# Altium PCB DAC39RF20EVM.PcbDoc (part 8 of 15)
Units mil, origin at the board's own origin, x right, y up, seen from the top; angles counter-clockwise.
Board outline 6200 x 2716.54 mil, 16 copper layers (Top Layer, L2 GND, L3 PWR, L4 GND, L5 PWR, L6 GND, L7 SIG, L8 GND, L9 GND, L10 SIG, L11 GND, L12 PWR, L13 GND, L14 PWR, L15 GND, Bottom Layer), stack 76.97 mil thick; 766 components, 495 nets, 3414 pads, 2373 vias.
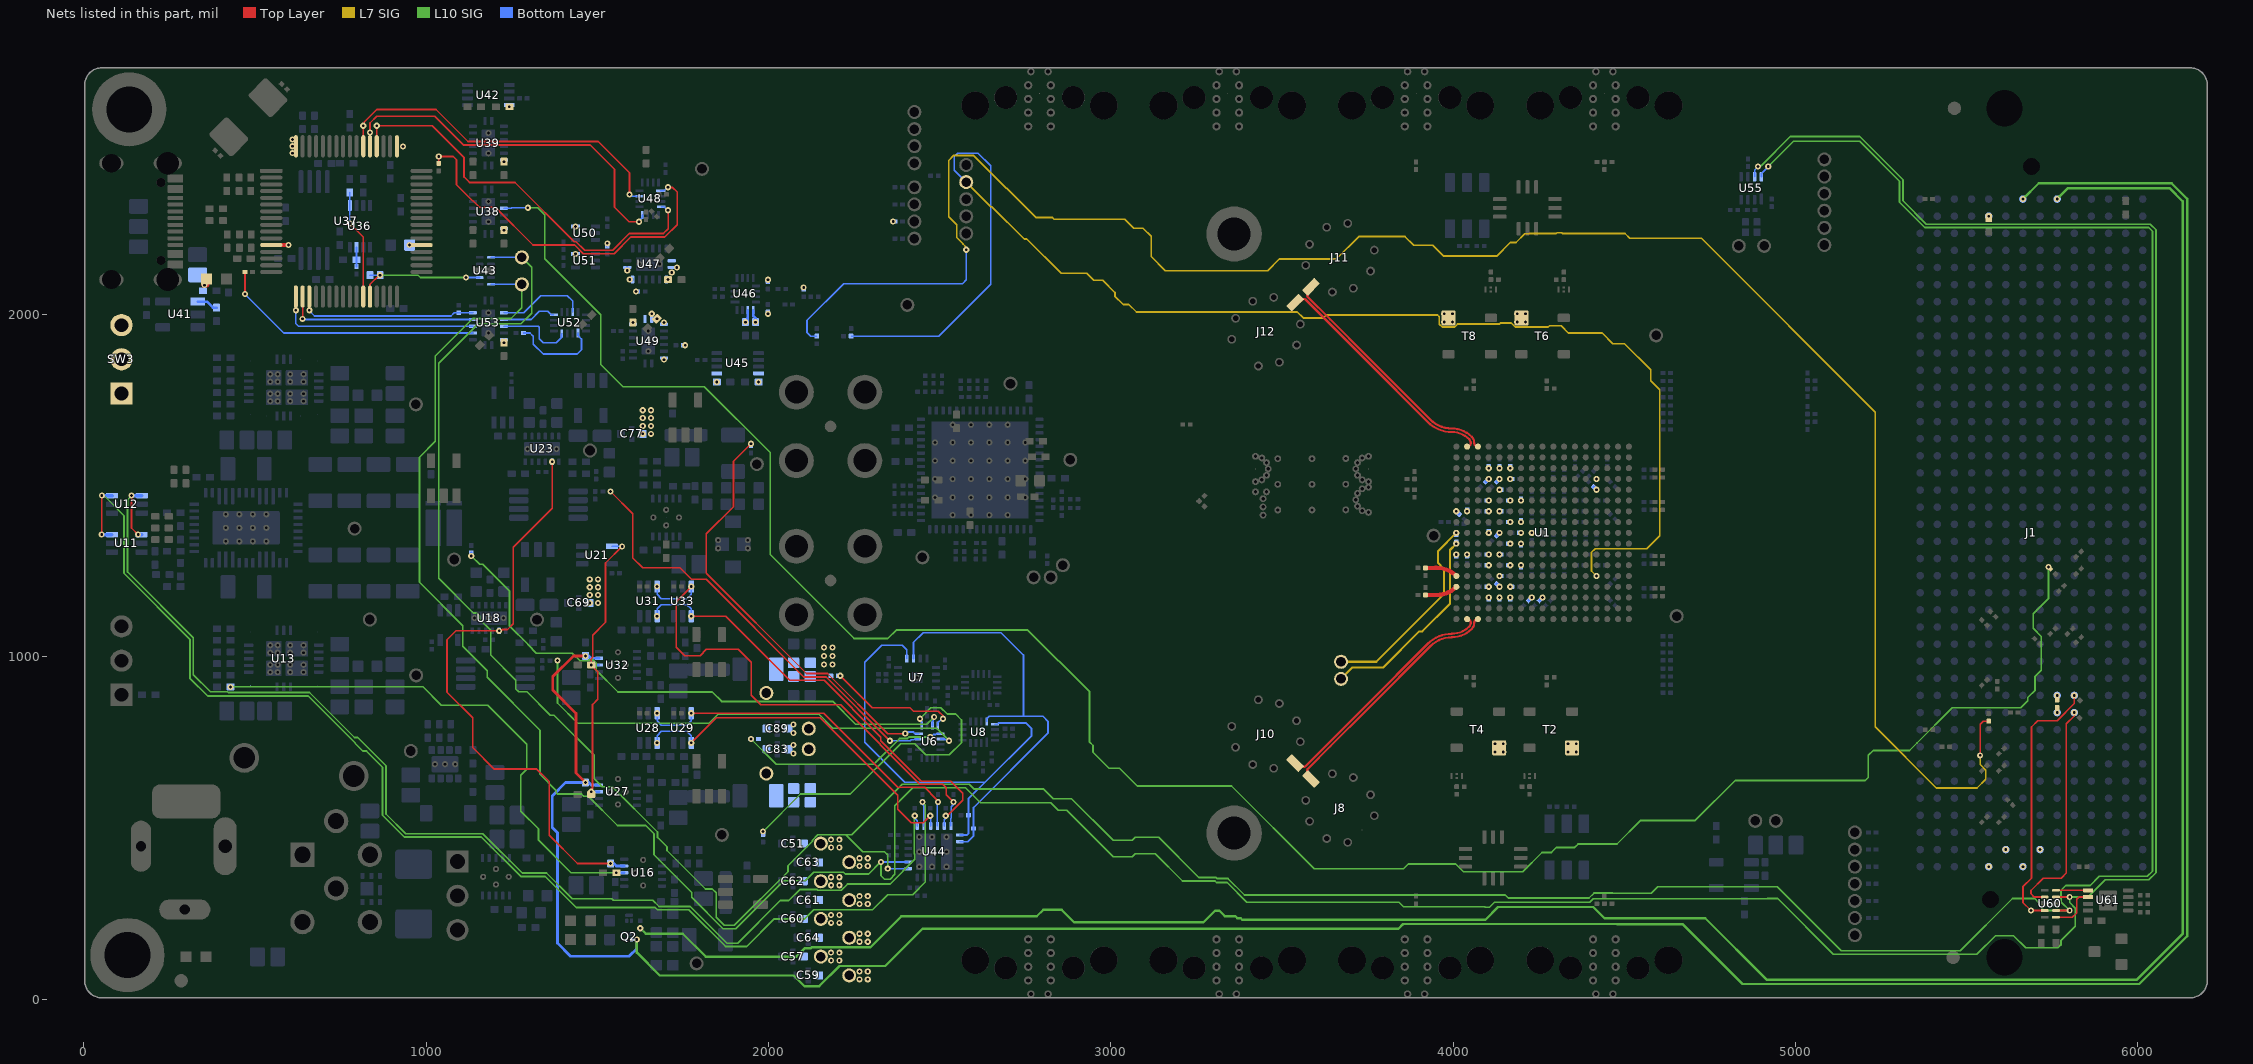
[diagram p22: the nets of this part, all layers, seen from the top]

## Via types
v1: diameter 18, hole 8, Top Layer to Bottom Layer, tented both sides, 2344 vias
v2: diameter 24, hole 12, Top Layer to Bottom Layer, tented both sides, 19 vias
v3: diameter 18, hole 8, Top Layer to Bottom Layer, tented bottom, 9 vias
v4: diameter 20, hole 10, Top Layer to Bottom Layer, tented both sides, 1 vias

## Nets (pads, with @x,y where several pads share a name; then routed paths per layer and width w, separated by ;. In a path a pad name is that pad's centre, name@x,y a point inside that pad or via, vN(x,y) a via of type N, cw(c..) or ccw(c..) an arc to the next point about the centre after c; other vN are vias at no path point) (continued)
PG-1p8V: R44.1 U16.4 U18.8 U23.8 | length 1756.8
  Top Layer w5: v1(1368.04,1569.83) 1368.04,1434.1 1253.99,1320.05 1253.99,1096.13 1237.52,1079.66 1222.91,1079.66 1220.98,1077.72 1215.14,1077.72 v1(1213.23,1075.81) 1087.27,1075.81 1060.61,1049.15 1060.61,897.35 1136.22,821.74 1136.22,734.92 1199.14,672 1322.98,672 1359.29,635.69 1359.29,478.91 1442.12,396.08 v1(1538.65,396.08)
  Bottom Layer w8: v1(1538.65,396.08) 1548.5,396.08 1555.58,388.99 U16.4@1578.58,388.99
PG-2p3V: R33.1 R45.1 U13.19 U16.3 | length 1533.3
  L10 SIG w5: v1(428.75,912.11) 990.96,912.11 1044.56,858.51 1180.09,858.51 1293.82,744.79 1293.82,671.96 1276.37,654.52 1276.37,549.02 1328.39,497 1328.39,464.12 1423.2,369.31 v1(1555.47,369.31)
  Bottom Layer w8: v1(1555.47,369.31) U16.3@1578.58,369.31
PG-C2M: J1.D1 R249.2 | length 7330.5
  L10 SIG w7: v1(1625.52,207.15) 1641.8,190.87 1749.69,190.87 1816.44,124.12 2081.09,124.12 2105.09,148.12 2122.78,148.12 2126.46,151.8 2297.87,151.8 2388.04,241.98 2783.51,241.98 2802.29,260.75 2856.47,260.75 2893.17,224.05 3270.01,224.05 3304.07,258.11 3316.91,258.11 3332.41,242.61 3363.13,242.61 3368.91,236.82 3378.95,236.82 3383.9,231.88 4094,231.88 4131.22,269.1 4409.18,269.1 4441.91,236.38 4736.03,236.38 4915.29,57.11 5996.92,57.11 6130.61,190.8 6130.61,2330.8 6092.38,2369.03 5795.97,2369.03 v1(5764.01,2337.07)
PG-M2C: J1.F1 Q2.1@1599.65,174.11 R68.1 R79.1 U27.4 U32.4 | length 8888.2
  Top Layer w8: v1(1465.29,632.63) 1437.66,660.25 1437.66,834.86 1369.67,902.85 1369.67,941.9 1430.39,1002.63 v1(1465.29,1002.63)
  L10 SIG w7: v1(1615.44,174.11) 1615.44,135.93 1682.25,69.12 2073.69,69.12 2105.02,37.8 2147.79,37.8 2206.86,96.87 2341.02,96.87 2449.88,205.73 3249.99,205.73 3250.4,205.32 3839.31,205.32 3853.18,219.19 3853.88,219.19 3854.07,219.38 4478.95,219.38 4479.13,219.19 4669.64,219.19 4844.71,44.11 6003.96,44.11 6143.61,183.76 6143.61,2337.84 6098.25,2383.2 5710.14,2383.2 v1(5664.01,2337.07)
  Bottom Layer w8: v1(1465.29,1002.63) 1475.13,1002.63 1482.21,995.54 U32.4@1505.21,995.54 ; U27.4@1505.21,625.54 1482.21,625.54 1475.13,632.63 v1(1465.29,632.63) 1407.43,632.63 1368.18,593.38 1368.18,501.72 1383.83,486.07 1383.83,163.62 1422.08,125.37 1592.76,125.37 1615.44,148.05 v1(1615.44,174.11) Q2.1@1599.65,174.11
PG-n1p8V: R69.1 R82.1 U21.4 U27.3 U32.3 | length 855.6
  Top Layer w5: v1(1482.1,605.86) 1484.59,608.34 1484.59,614.16 1485.71,615.28 1485.71,860.44 1501.62,876.34 1501.62,956.34 1491.41,966.54 1491.41,968.51 1484.07,975.86 v1(1482.1,975.86) 1482.1,994.43 1486.68,999.01 1486.68,1063.36 1523.93,1100.61 1523.93,1274 v1(1572.44,1322.51)
  Top Layer w8: R69.1@1482.1,597.86 v1(1482.1,605.86)
  Bottom Layer w5: v1(1482.1,975.86) U32.3@1505.21,975.86 ; U21.4@1542.44,1322.51 v1(1572.44,1322.51)
  Bottom Layer w8: v1(1482.1,605.86) U27.3@1505.21,605.86
PROG_B_SHIFT: R200.1 U38.12 | length 6406.3
  Top Layer w5: v3@5738.71,1262.37 R200.1@5743.72,1257.36
  L10 SIG w5: v1(1297.12,2311.69) 1325.64,2311.69 1346.41,2290.92 1346.41,2162.73 1509.79,1999.35 1509.79,1853.93 1574.99,1788.73 1812.78,1788.73 2004.81,1596.71 2004.81,1315.82 2004.81,1298.6 2249.97,1053.44 2348.3,1053.44 2372.84,1077.99 2757.27,1077.99 2937.83,897.43 2937.83,750.89 2947.73,741 2947.73,721.35 2994.4,674.68 3025.37,674.68 3077.27,622.78 3352.22,622.78 3594.09,380.91 3854.57,380.91 3868.56,394.89 4007.37,394.89 4029.79,372.47 4203.22,372.47 4259.15,428.39 4286.77,428.39 4301.63,443.26 4354.84,443.26 4364.67,453.09 4478.53,453.09 4547.52,522.08 4706.71,522.08 4823.43,638.8 5203.82,638.8 5212.61,647.59 5212.61,712.07 5226.66,726.12 5332.56,726.12 5354.45,748.02 5458.01,851.57 5658.06,851.57 5678.51,872.02 5678.51,881.06 5699.51,902.06 5699.51,943.07 5717.59,961.16 5717.59,1059.35 5693.87,1083.07 5693.87,1125.44 5739.01,1170.58 5739.01,1261.82 v3(5738.58,1262.25)
  Bottom Layer w5: U38.12@1227.12,2310.19 1248.54,2310.19 1250.04,2311.69 v1(1297.12,2311.69)
PRSNT-M2C-L: J1.H2 R220.2 | length 5.3
  Top Layer w10: R220.2@5564.01,2281.75 v1(5564.01,2287.07)
RB+: PP54.1 R175.1 U1.J17 | length 590.2
  L7 SIG w6.3: PP54.1@3672.29,985.47 3775.37,985.47 3972.67,1182.78 3972.67,1257.03 3955.91,1273.79 3955.91,1308.85 v1(4009.03,1361.97)
RB-: PP47.1 R175.2 U1.H17 | length 597
  L7 SIG w6.3: PP47.1@3672.29,935.47 3705.39,968.56 3795.34,968.56 3901.04,1074.26 3909.77,1074.26 3990.37,1154.86 3990.37,1311.81 v1(4009.03,1330.47)
  Bottom Layer w6.3: v1(4009.03,1330.47) R175.2@4009.03,1335.2
S\Y\N\C\_DAC: PP59.1 R250.2 R253.2 U1.E4 | length 4085.8
  L7 SIG w5: PP59.1@2577.51,2386.45 2649.04,2314.92 2652.38,2314.92 2746.96,2220.34 2754.48,2220.34 2854.67,2120.15 2929.05,2120.15 2949.56,2099.65 2976.19,2099.65 3011.77,2064.07 3011.77,2053.43 3035.98,2029.22 3052.5,2029.22 3074.81,2006.91 3544.41,2006.91 3561.5,1989.82 3620.37,1989.82 3628.91,1998.36 3954.04,1998.36 3959.49,1992.91 3959.49,1971.84 3967.98,1963.34 4003.99,1963.34 4012.49,1971.84 4134.39,1971.84 4137.51,1974.96 4169.38,1974.96 4180.99,1963.34 4277.48,1963.34 4281.3,1967.16 4315.17,1967.16 4336.38,1945.96 4434.86,1945.96 4466.33,1914.49 4500.38,1914.49 4576.75,1838.12 4576.75,1806.71 4603.1,1780.36 4603.1,1353.8 4565.27,1315.97 4414.97,1315.97 4403.98,1304.98 4403.98,1250.48 v1(4418.48,1235.98)
  Bottom Layer w5: R253.2@2241.26,1936.55 2497.12,1936.55 2649.04,2088.47 2649.04,2433.88 2611.77,2471.15 2552.54,2471.15 2542.51,2461.12 2542.51,2421.46 PP59.1@2577.51,2386.45
S\Y\N\C\_FMC: R225.1 R226.1 R251.2 R252.2 | length 5671.9
  Top Layer w5: v1(5539.01,712.07) 5539.01,802.66 5548.42,812.07 R226.1@5564.01,812.07
  L7 SIG w5: v1@2577.51,2186.45 2577.51,2196.19 2567.91,2205.79 2567.91,2206.45 2549.51,2224.85 2549.51,2262.14 2526.19,2285.46 2526.19,2449.77 2540.87,2464.45 2598.11,2464.45 2694.17,2368.4 2695.44,2368.4 2780.44,2283.4 2828.53,2283.4 2833.82,2278.11 3040.79,2278.11 3067.12,2251.77 3094.01,2251.77 3117.73,2228.05 3117.73,2169.32 3159.25,2127.8 3458.34,2127.8 3492.28,2161.74 3658.56,2161.74 3724.22,2227.4 3859.29,2227.4 3884.2,2202.49 3940.66,2202.49 3972.67,2170.47 4126.89,2170.47 4166.52,2210.1 4183.51,2210.1 4209.12,2235.71 4222.51,2235.71 4223.06,2236.26 4300.94,2236.26 4302.94,2238.26 4316.61,2238.26 4318.61,2236.26 4501.76,2236.26 4515.78,2222.24 4725.17,2222.24 5232.61,1714.81 5232.61,795.43 5411.29,616.75 5530.02,616.75 5555.51,642.24 5555.51,668.9 5539.01,685.4 v1(5539.01,712.07)
  Bottom Layer w5: R251.2@2141.26,1936.55 2123.45,1936.55 2112.1,1947.9 2112.1,1982.26 2219.85,2090 2566.51,2090 2577.51,2101 v1@2577.51,2186.45
  other v1: 2577.61,2188.8
SCL-ADC: R126.1 U7.14 U8.12 U44.8 | length 1253.6
  Bottom Layer w5: U7.14@2423.67,994.53 2423.67,1042.44 2451.75,1070.53 2679.1,1070.53 2744.51,1005.11 2744.51,826.09 ; U44.8@2558.93,459.96 2581.79,459.96 2599.02,477.19 R126.1@2599.02,498.34 2599.02,559.8 2816.11,776.88 2816.11,811.69 2801.7,826.09 2744.51,826.09 ; U8.12@2637.46,811.09 2637.46,818.96 2644.58,826.09 2744.51,826.09
SCL-DVDD: R120.1 U11.3 U12.3 U44.2 | length 3760.4
  Top Layer w5: v1(52.17,1356.94) 52.8,1357.57 v1(52.8,1470.93)
  L10 SIG w5: v1(52.8,1470.93) 58.89,1470.93 117.61,1412.22 117.61,1243.76 309.92,1051.44 309.92,937.67 361.98,885.61 655.31,885.61 792.74,748.18 792.74,746.8 814.64,724.9 825.45,724.9 872.61,677.74 872.61,536.87 935.95,473.53 1161.33,473.53 1276.37,358.48 1347.26,358.48 1438.05,267.69 1668.83,267.69 1675.77,260.75 1767.51,260.75 1874.65,153.62 1936.43,153.62 2017.17,234.37 2105.72,234.37 2132.1,260.75 2303.84,260.75 2348.44,305.35 2420.92,305.35 2457.79,342.22 2457.79,566.29 2449.61,574.48 v1(2449.61,575.72)
  Bottom Layer w5: v1(2449.61,575.72) 2449.61,568.64 2454.11,564.14 U44.2@2454.11,505.72
  Bottom Layer w10: v1(52.17,1356.94) U11.3@82.17,1356.94 ; v1(52.8,1470.93) U12.3@82.8,1470.93
SCL-VDDCLK: R124.1 U31.3 U33.3 U44.6 | length 1505.8
  Top Layer w4: v1(1774.54,1205.18) 1730.58,1161.22 1730.58,1027.59 1754.73,1003.44 1800.07,1003.44 1818.37,1021.74 1911.45,1021.74 1948.93,984.26 1948.93,887.3 1977,859.24 2210.59,859.24 2442.06,627.77 2508.66,627.77 2518.69,617.74 2518.69,597.38 v1(2540.35,575.72)
  Bottom Layer w4: v1(1674.55,1205.18) 1674.55,1182.48 1687.41,1169.63 1761.69,1169.63 1774.54,1182.48 v1(1774.54,1205.18) ; U44.6@2532.85,505.72 2532.85,528.28 2533.66,529.1 2533.66,561.95 2540.35,568.64 v1(2540.35,575.72)
SCL-VDDL: R122.1 U28.3 U29.3 U44.4 | length 1057.1
  Top Layer w4: v1(1774.54,835.18) 2161.64,835.18 2378.05,618.77 2456.24,618.77 2490.52,584.48 2490.52,583.97 2494.98,579.51 v1(2494.98,575.72)
  Bottom Layer w4: v1(1674.54,835.18) 1674.54,812.48 1687.4,799.63 1761.68,799.63 1774.54,812.48 v1(1774.54,835.18) ; U44.4@2493.48,505.72 2493.48,567.14 2494.98,568.64 v1(2494.98,575.72)
SCL_EEPROM: U60.6 U61.6 | length 141.8
  Top Layer w5: U60.6@5760.47,239.11 5808.37,239.11 5820.82,251.56 5820.82,291.57 5827.42,298.16 U61.6@5854.4,298.16
SCL_I2C: PP31.1 U43.6 U44.19 U55.8 U60.7 | length 10921.4
  Top Layer w5: U60.7@5760.47,258.79 v1(5800.47,258.8)
  L10 SIG w5: PP31.1@1279.44,2166.77 1308.25,2137.96 1308.25,2003.6 1277.12,1972.47 1152.08,1972.47 1036.92,1857.32 1036.92,1229.04 1138.31,1127.65 1147.36,1127.65 1155.81,1119.19 1155.81,1110.15 1188.36,1077.6 1188.36,1005.12 1261.79,931.69 1261.79,906.1 1270.28,897.61 1294.45,897.61 1362.83,829.22 1373.52,829.22 1490.71,712.03 1490.71,644.22 1514.64,620.29 1543.67,620.29 1675.68,488.29 1675.68,472.4 1703.39,444.69 1703.39,434.33 1815.89,321.82 1835.89,321.82 1847.3,310.42 1847.3,239.42 1870.99,215.73 1900.26,215.73 2056.86,372.33 2056.86,389.63 2128.36,461.12 2128.36,464.52 2144.21,480.37 2225.53,480.37 ; v1(2348.34,381.21) 2348.34,421.38 2338.95,430.78 2275.13,430.78 2225.53,480.37 ; v1(4920.11,2432.07) 4993.85,2505.8 5186.91,2505.8 5303.61,2389.1 5303.61,2327.96 5377.77,2253.8 6031.71,2253.8 6042.61,2242.9 6042.61,373.8 6027.61,358.8 5887.4,358.8 5860.62,332.02 5789.59,332.02 5774.97,317.4 5774.97,284.3 v1(5800.47,258.8) 5726.77,258.8 5711.97,273.59 5711.97,279.89 5698.06,293.8 5633.41,293.8 5481.03,141.42 5133.37,141.42 4946.39,328.4 4597.84,328.4 4578.53,309.09 4466.52,309.09 4465.79,309.82 4410.97,309.82 4396.47,295.32 4160.82,295.32 4151.77,304.38 3867.05,304.38 3866.73,304.05 3390.3,304.05 3342.2,352.16 3311.18,352.16 3308.12,355.22 3256.84,355.22 3139.57,472.49 3070.99,472.49 3062.42,463.93 3006.5,463.93 2884.94,585.48 2831.71,585.48 2803.65,613.55 2600.52,613.55 2586.6,627.47 2390.59,627.47 2243.49,480.37 2225.53,480.37
  Bottom Layer w5: U43.6@1189.44,2166.77 PP31.1@1279.44,2166.77 ; v1(2348.34,381.21) U44.19@2408.34,381.21 ; U55.8@4900.11,2402.07 4900.11,2410.92 4920.11,2430.92 v1(4920.11,2432.07)
SCL_Local: J1.C30 R208.2 U60.4 | length 774.6
  Top Layer w5: U60.4@5727.59,258.79 v1(5687.59,258.79) 5664.01,282.37 5664.01,328.6 5688.91,353.5 5688.91,795.14 5707.25,813.49 5763.76,813.49 5814.01,863.73 5814.01,878.63 5812.48,880.16 5812.48,885.54 v1(5814.01,887.07)
SDA-ADC: R125.1 U7.13 U8.13 U44.7 | length 1333.9
  Bottom Layer w5: U7.13@2403.98,994.53 2403.98,1020.75 2390.97,1033.76 2330.72,1033.76 2281.22,984.26 2281.22,750.17 2397.46,633.92 2632.47,633.92 ; U44.7@2558.93,479.64 2580.68,479.64 2583.92,482.88 R125.1@2583.92,537.41 2583.92,585.37 2632.47,633.92 ; U8.13@2661.08,803.21 2668.95,803.21 2672.6,806.86 2751.25,806.86 2768.41,789.7 2768.41,769.86 2632.47,633.92
SDA-DVDD: R119.1 U11.4 U12.4 U44.1 | length 3548.3
  Top Layer w5: v1(139.41,1470.93) 139.41,1376.31 v1(158.78,1356.94)
  L10 SIG w5: v1(139.41,1470.93) 127.61,1459.13 127.61,1247.9 319.92,1055.59 319.92,947.6 369.92,897.61 419.92,897.61 421.91,895.61 659.45,895.61 790.62,764.44 800.05,764.44 882.61,681.89 882.61,541.01 940.09,483.53 1165.47,483.53 1280.51,368.48 1351.4,368.48 1426.57,293.31 1541.94,293.31 1546.58,288.67 1662,288.67 1679.91,270.75 1771.66,270.75 1878.79,163.62 1909.8,163.62 2034.3,288.12 2058.92,288.12 2090.85,320.05 2142.53,320.05 2144.21,318.37 2212.86,318.37 2230.96,336.47 2355.17,336.47 2426.92,408.22 2426.92,423.42 2425.89,424.45 2425.89,534.69 v1(2426.92,535.72)
  Bottom Layer w5: v1(2426.92,535.72) 2426.92,528.64 2434.42,521.14 U44.1@2434.42,505.72
  Bottom Layer w10: v1(139.41,1470.93) U12.4@169.41,1470.93 ; v1(158.78,1356.94) U11.4@168.78,1356.94
SDA-VDDCLK: R123.1 U31.4 U33.4 U44.5 | length 1291.6
  Top Layer w4: v1(1774.54,1118.57) 1874.86,1118.57 2061.85,931.57 2162.1,931.57 2328.34,765.33 2328.34,754.21 2445.79,636.77 2532.98,636.77 2567.61,602.15 2567.61,580.35 2526.93,539.67 2525.4,539.67 2521.45,535.72 v1(2517.66,535.72)
  Bottom Layer w4: U31.4@1674.55,1117.07 v1(1674.55,1118.57) 1674.55,1139.76 1687.41,1152.62 1761.69,1152.62 1774.54,1139.76 v1(1774.54,1118.57) U33.4@1774.54,1117.07
  Bottom Layer w5: U44.5@2513.16,505.72 2513.16,524.14 2517.66,528.64 v1(2517.66,535.72)
SDA-VDDL: R121.1 U28.4 U29.4 U44.3 | length 1074.2
  Top Layer w4: v1(1774.54,748.57) 1847.77,821.8 2151.39,821.8 2378.05,595.13 2378.05,554.34 2417.29,515.11 2451.68,515.11 v1(2472.29,535.72)
  Bottom Layer w4: U28.4@1674.54,747.07 v1(1674.54,748.57) 1674.54,769.76 1687.4,782.62 1761.68,782.62 1774.54,769.76 U29.4@1774.54,747.07
  Bottom Layer w5: v1(2472.29,535.72) 2472.29,528.64 2473.79,527.14 U44.3@2473.79,505.72
SDA_EEPROM: U60.10 U61.5 | length 93.9
  Top Layer w5: U60.10@5760.47,317.85 5820.82,317.85 U61.5@5854.4,317.85
SDA_I2C: PP30.1 U43.10 U44.20 U55.7 U60.9 | length 10986.1
  Top Layer w5: U60.9@5760.47,298.16 v1(5800.47,298.17)
  L10 SIG w5: PP30.1@1279.44,2088.03 1279.44,2019.89 1247.78,1988.22 1136.57,1988.22 1026.92,1878.57 1026.92,1629.45 980.41,1582.94 980.41,1217.37 1107.02,1090.76 1107.02,1030.42 1178.36,959.08 1178.36,940.06 1332.55,785.86 1332.55,656.93 1380.28,609.2 1380.28,601.98 1383.21,599.05 1453.7,599.05 1460.16,592.59 1473.8,592.59 1558.95,507.43 1641.77,507.43 1665.68,483.52 1665.68,421.38 1775.39,311.67 1775.39,297.2 1866.85,205.73 1904.4,205.73 2044.3,345.62 2106.85,345.62 2132.1,370.87 2219.01,370.87 2224.51,365.37 2292.82,365.37 v1(2328.34,400.9) 2328.34,361.22 2338.95,350.61 2355.17,350.61 2368.98,364.42 2368.98,565.33 2420.92,617.27 2575.37,617.27 2619.24,573.4 2824.14,573.4 2846.01,551.54 2871.21,551.54 3006.83,415.93 3062.42,415.93 3070.99,424.49 3129.95,424.49 3209.22,345.22 3303.98,345.22 3308.65,340.54 3339.67,340.54 3396.92,283.3 3841.47,283.3 3854.72,270.05 4092.67,270.05 4093.93,268.8 4105.94,268.8 4120.44,283.3 4398.59,283.3 4408.6,293.3 4917.61,293.3 ; v1(4890.43,2432.07) 4892.91,2434.55 4899.27,2434.55 4984.51,2519.8 5187.05,2519.8 5313.61,2393.24 5313.61,2332.1 5381.91,2263.8 6035.85,2263.8 6052.61,2247.05 6052.61,369.66 6031.75,348.8 5904.46,348.8 5853.83,298.17 v1(5800.47,298.17) 5800.47,282.13 5816.97,265.63 5816.97,212.44 5774.97,170.44 5774.97,158.42 5766.47,149.93 5671.89,149.93 5636.29,185.52 5583.73,185.52 5529.63,131.42 5109.99,131.42 4947.61,293.8 4917.61,293.8
  Bottom Layer w5: U43.10@1189.44,2088.03 PP30.1@1279.44,2088.03 ; v1(2328.34,400.9) U44.20@2408.34,400.9 ; U55.7@4880.43,2402.07 4880.43,2422.07 v1(4890.43,2432.07)
SDA_Local: J1.C31 R209.2 U60.2 | length 656.6
  Top Layer w5: U60.2@5727.59,298.16 5697.23,298.16 5687.59,307.79 5687.59,317.43 5723.66,353.5 5775.74,353.5 5790.82,368.57 5790.82,804.38 5814.57,828.12 5814.57,836.51 v1(5814.01,837.07)
SYSREF_N: R173.1 R174.1 U1.E17 | length 96.4
  Top Layer w12.1: R173.1@3919.03,1259.85 3947.29,1259.85
  Top Layer w12.3: 3947.29,1259.85 3951.42,1259.85 cw(c3951.42,1178.38) U1.E17@4009.03,1235.98
SYSREF_P: R171.1 R172.1 U1.D17 | length 96.4
  Top Layer w12.1: R171.1@3919.03,1180.63 3947.29,1180.63
  Top Layer w12.3: 3947.29,1180.63 3951.42,1180.63 ccw(c3951.42,1262.1) U1.D17@4009.03,1204.49
TDI_FMC: J1.D30 R207.2 | length 13.3
  Top Layer w10: R207.2@5764.01,873.78 v1(5764.01,887.07)
TDO_FMC: J1.D31 R207.1 | length 14.7
  Top Layer w10: v1(5764.01,837.07) R207.1@5764.01,851.73
TMSTPA_N: J10.1 U1.A16 | length 702.5
  Top Layer w6.3: J10.1@3538.34,689.32 3543.09,689.32 cw(c3543.09,671.21) 3555.89,684.01 3559.35,680.56 ccw(c3563.8,685.01) 3563.8,678.71 ccw(c3563.8,685.01) 3568.26,680.56 3742.05,854.35 3926.44,1038.74 cw(c3995.5,969.68) 3995.5,1067.34 ccw(c3995.5,1139.63) 4046.61,1088.51 ccw(c4035.72,1099.4) 4051.12,1099.4 ccw(c4040.52,1099.4) U1.A16@4040.52,1110
TMSTPA_P: J8.1 U1.A15 | length 710.6
  Top Layer w6.3: J8.1@3575.54,664.36 3579,660.91 cw(c3566.2,648.1) 3584.3,648.1 J8.1@3584.3,643.36 ; J8.1@3575.54,664.37 cw(c3580,668.82) 3573.7,668.82 cw(c3580,668.82) 3575.54,673.27 3640.69,738.43 3749.34,847.07 3933.72,1031.45 cw(c3995.5,969.68) 3995.5,1057.04 ccw(c3995.5,1139.63) 4053.9,1081.23 ccw(c4035.72,1099.4) 4061.42,1099.4 cw(c4072.02,1099.4) U1.A15@4072.02,1110
TMSTPB_N: J12.1 U1.U16 | length 702.5
  Top Layer w6.3: J12.1@3538.34,2034.62 3543.09,2034.62 ccw(c3543.09,2052.72) 3555.89,2039.92 3559.35,2043.38 cw(c3563.8,2038.93) 3563.8,2045.22 cw(c3563.8,2038.92) 3568.26,2043.38 3742.05,1869.59 3926.44,1685.2 ccw(c3995.5,1754.26) 3995.5,1656.59 cw(c3995.5,1584.31) 4046.61,1635.42 cw(c4035.72,1624.53) 4051.12,1624.53 cw(c4040.52,1624.53) U1.U16@4040.52,1613.94
TMSTPB_P: J11.1 U1.U15 | length 710.6
  Top Layer w6.3: J11.1@3584.3,2080.58 3584.3,2075.83 cw(c3566.2,2075.83) 3579,2063.03 3575.54,2059.57 ccw(c3580,2055.12) 3573.7,2055.12 ccw(c3580,2055.12) 3575.54,2050.66 3640.69,1985.51 3749.34,1876.87 3933.72,1692.48 ccw(c3995.5,1754.26) 3995.5,1666.89 cw(c3995.5,1584.31) 4053.9,1642.71 cw(c4035.72,1624.53) 4061.42,1624.53 ccw(c4072.02,1624.53) U1.U15@4072.02,1613.94
USB_5V: C132.2 D4.1 R104.2 R117.2 U41.1 | length 84.4
  Top Layer w18: v1(352.41,2085.55) 354.92,2088.05 358.07,2088.05 D4.1@358.07,2103.8
  Bottom Layer w8: U41.1@332.71,2037.39 359.77,2037.39 377.48,2019.67 R117.2@387.33,2019.67
USB_C\S\_DAC_3p3: R152.2 U37.19 U53.6 | length 529.3
  Top Layer w5: v1(658.81,2012.12) U37.19@658.81,2052.12
  Bottom Layer w5: v1(658.81,2012.12) 658.81,2010.66 673.85,1995.62 1072.67,1995.62 1081.93,2004.88 R152.2@1095.32,2004.88 U53.6@1136.57,2004.88
USB_C\S\_LMK_3p3: U37.54 U48.11 | length 1034.1
  Top Layer w5: U37.54@816.3,2491.1 v1(816.3,2551.1) 818.78,2553.58 818.78,2561.92 855.67,2598.8 1028.68,2598.8 1122.27,2505.21 1502.64,2505.21 1593.74,2414.11 v1(1593.74,2350.62)
  Bottom Layer w5: v1(1593.74,2350.62) 1597.26,2350.62 1602.26,2345.62 U48.11@1623.74,2345.62
USB_CS_DAC_1p8: U52.11 U53.11 | length 260.6
  Bottom Layer w5: U53.11@1227.12,2004.88 1284.79,2004.88 1334.88,2054.96 1412.46,2054.96 1427.99,2039.43 U52.11@1427.99,2006.84
USB_I2C_SCL: R97.1 R102.2 U36.7 | length 56
  Bottom Layer w5: R102.2@796.61,2140.02 796.61,2147.1 R97.1@796.61,2160.02 796.61,2169.86 U36.7@796.61,2196.02
USB_I2C_SDAr: R101.2 R103.2 U37.28 U43.2 | length 400
  Top Layer w5: U37.28@835.98,2052.12 835.98,2088.15 v1@862.51,2114.68
  L10 SIG w5: v1@862.51,2114.68 v1(865.51,2114.68) 976.32,2114.68 983.29,2107.71 v1(1116.57,2107.71)
  Bottom Layer w5: R103.2@835.98,2114.68 v1(865.51,2114.68) ; v1(1116.57,2107.71) U43.2@1156.57,2107.71
USB_I2C_SDAw: R100.1 U36.1 U37.27 | length 320.3
  Top Layer w5: v1(776.93,2265.66) 816.3,2226.29 U37.27@816.3,2052.12
  Bottom Layer w5: v1(776.93,2265.66) U36.1@776.93,2318.07 R100.1@776.93,2356.07
USB_SCLK_DAC_1p8: R153.2 U52.1 | length 265
  Bottom Layer w5: R153.2@1284.17,1945.82 1303.46,1945.82 1312.73,1936.55 1312.73,1913.33 1341.71,1884.34 1441.61,1884.34 1453.74,1896.47 1453.74,1925.82 ; U52.1@1443.74,1945.82 1443.74,1937.95 1453.74,1927.95
USB_SCLK_DAC_3p3: R99.2 U53.3 | length 777.4
  Top Layer w5: v1(470.55,2059.75) R99.2@470.55,2123.97
  Bottom Layer w5: v1(470.55,2059.75) 584.47,1945.82 U53.3@1136.57,1945.82
USB_SCLK_LMK_3p3: R107.2 U48.1 | length 1065.3
  Top Layer w5: R107.2@1036.57,2441.29 v1(1036.57,2461.29) 1079.15,2461.29 1088.82,2451.62 1088.82,2378.98 1135.56,2332.24 1136.96,2332.24 1155.76,2313.44 1201.51,2313.44 1312.24,2202.71 1433.59,2202.71 1458.73,2177.58 1549.05,2177.58 1597.76,2226.29 1697.1,2226.29 1733.23,2262.43 1733.23,2357.46 1720.21,2370.48 1707.62,2370.48 v1(1706.73,2371.37)
  Bottom Layer w5: U48.1@1684.76,2361.37 1694.61,2361.37 1704.61,2371.37 v1(1706.73,2371.37)
USB_SDI_DAC_1p8: U52.4 U53.13 | length 225.7
  Bottom Layer w5: U53.13@1227.12,1965.51 1327.35,1965.51 1330.28,1962.58 1330.28,1928.95 1341.75,1917.48 1380.12,1917.48 1395.06,1932.42 1395.06,1942.42 U52.4@1396.49,1943.85
USB_SDI_DAC_3p3: U37.17 U53.4 | length 599.2
  Top Layer w5: v1(619.44,2012.12) U37.17@619.44,2052.12
  Bottom Layer w5: v1(619.44,2012.12) 619.44,1973.33 627.27,1965.51 U53.4@1136.57,1965.51
USB_SDI_LMK_3p3: U37.52 U48.4 | length 1198.9
  Top Layer w5: U37.52@855.67,2491.1 v1(855.67,2551.1) 1017.74,2551.1 1110.82,2458.01 1110.82,2401.41 1126.84,2385.39 1259.49,2385.39 1432.16,2212.71 1437.74,2212.71 1462.87,2187.58 1544.9,2187.58 1593.62,2236.29 1692.95,2236.29 1706.73,2250.07 v1(1706.73,2304.13)
  Bottom Layer w5: U48.4@1686.73,2314.13 1694.61,2314.13 1704.61,2304.13 v1(1706.73,2304.13)
USB_SDO_DAC_1p8: U52.8 U53.12 | length 159.7
  Bottom Layer w5: U53.12@1227.12,1985.19 1306.5,1985.19 1330.28,2008.97 1355,2008.97 1365,1998.97 U52.8@1372.87,1998.97
USB_SDO_DAC_3p3: U37.18 U53.5 | length 558.2
  Top Layer w5: v1@639.13,1992.12 U37.18@639.13,2052.12
  Bottom Layer w5: v1(639.13,1987.12) 641.06,1985.19 U53.5@1136.57,1985.19
USB_SDO_LMK_3p3: U37.53 U48.8 | length 1078.6
  Top Layer w5: U37.53@835.98,2491.1 v1(835.98,2531.1) 835.98,2559.05 855.67,2578.73 1024.97,2578.73 1108.49,2495.21 1478.64,2495.21 1550.13,2423.72 1550.13,2312.71 1592.33,2270.51 v1(1621.61,2270.51)
  Bottom Layer w5: v1(1621.61,2270.51) 1621.61,2272.63 1631.61,2282.63 U48.8@1631.61,2290.51
VADJ: C120.2 C122.2 C134.2 J1.E39 J1.F40 J1.G39 J1.H40 pad.1@282.86,1921.82 pad.1@1947.86,2491.82 SW3.2 U38.15 U39.15 U42.8 | length 15
  Bottom Layer w5: v1(1227.12,2246.14) U38.15@1227.12,2251.14 ; v1(1227.12,2446.14) U39.15@1227.12,2451.14 ; v1(1242.87,2606.41) U42.8@1242.87,2611.41
  other v1: 5564.01,387.07 5664.01,387.07 5614.01,437.07 5714.01,437.07
VCORE: C118.2 pad.1@647.86,2376.82 U37.12 U37.37 U37.49 U37.64 | length 84.5
  Top Layer w5: v1(951.57,2202.71) U37.37@986.1,2202.71
  Top Layer w12: U37.12@547.59,2202.71 v1(597.59,2202.71)
  other v1: 609.44,2471.1 932.59,2490.65 609.44,2491.1 609.44,2511.1
VDD_FPGA: C136.1 C139.1 C141.1 C143.1 pad.1@927.86,1936.82 R132.1 R133.1 R134.1 R139.1 R140.1 SW3.1 U45.1 U46.13 U47.1 U47.2 U47.7 U47.8 U47.16 U49.1 U49.2 U49.7 U49.16 | length 95.2
  Bottom Layer w8: v1(1587.39,2128.6) U47.8@1587.39,2137.26 ; v1(1594.48,2101.83) U47.7@1603.14,2101.83 ; v1(1694.38,1867.99) U49.7@1694.38,1872.99 ; U49.2@1694.38,1971.41 v1(1694.38,1976.41) ; U47.2@1701.57,2101.83 v1(1706.57,2101.83) ; U46.13@1955.28,2012.46 1955.28,1996.27 1962.28,1989.27 v1(1962.28,1977.46)
  Bottom Layer w12: v1(1612.97,2066.83) R140.1@1617.97,2066.83 ; R139.1@1751.43,1909.86 v1(1756.43,1909.86) ; v1(1998.15,2002.18) R134.1@1998.15,2007.18 ; R132.1@1998.15,2096.47 v1(1998.15,2101.47) ; R133.1@2102.61,2073.87 v1(2102.61,2078.87)
  other v1: 1848.98,1802.71 1673.95,1987.16 1658.95,2002.16 1717.32,2122.26 1732.32,2137.26
VDDA18A: C63.3 C289.1 C290.1 pad.1@3345.34,601.99 PP21.1 T2.3 T4.3 U1.G16 U1.G17
  other v1: 2265.74,388.63 2289.75,388.64 2265.74,411.63 2289.74,411.64 4122.02,722.09 4146.02,722.09 4335.03,722.09 4359.03,722.09 4122.02,746.09 4146.02,746.09 4335.03,746.09 4359.03,746.09 4009.03,1298.98 4040.52,1298.98
VDDA18B: C64.3 C287.1 C288.1 pad.1@3619.67,221.32 PP22.1 T6.3 T8.3 U1.L16 U1.L17 | length 11.2
  Bottom Layer w8: v1(4009.03,1424.96) C288.1@4016.98,1417.01
  other v1: 2265.75,167.87 2289.75,167.87 2265.75,190.87 2289.75,190.87 4040.52,1424.96 3973.99,1977.84 3997.99,1977.84 4187,1977.84 4211,1977.84 3973.99,2001.84 3997.99,2001.84 4187,2001.84 4211,2001.84
VDDCLK08: C95.2 C96.2 C97.2 C98.2 C306.1 C307.1 C308.1 C309.1 C310.1 C311.1 C312.1 C313.1 C314.1 FB5.2 pad.1@3073.23,1288.31 PP28.1 R78.1 U1.E13 U1.F12 U1.G13 U1.H12 U1.J11 U1.K12 U1.L13 U1.M12 U1.N13 | length 44.8
  Bottom Layer w5: v1@2186.28,1029.46 ccw(c2189.09,1029.46) v1(2187.1,1027.47) ; v1(2187.1,1002.47) v1@2187.18,1002.39 ; v1(4135.01,1235.98) C314.1@4139.74,1235.98 ; v1(4135.01,1298.98) C312.1@4139.74,1298.98 ; v1(4135.01,1424.96) C308.1@4139.74,1424.96 ; v1(4135.01,1487.95) C306.1@4139.74,1487.95 ; C313.1@4161.78,1267.48 v1(4166.51,1267.48) ; C311.1@4161.78,1330.47 v1(4166.51,1330.47) ; C309.1@4161.78,1393.46 v1(4166.51,1393.46) ; C307.1@4161.78,1456.46 v1(4166.51,1456.46) ; C310.1@4193.28,1361.97 v1(4198,1361.97)
  other v1: 2162.1,977.47 2187.1,977.47 2162.1,1002.47 2162.1,1027.47
VDDCLK18: C62.3 C291.1 C292.1 pad.1@2807.86,1076.82 PP20.1 U1.L14 U1.M14
  other v1: 2182.86,332.87 2206.86,332.87 2182.86,355.87 2206.86,355.87 4103.52,1424.96 4103.52,1456.46
VDDCP18: C61.3 C282.1 C283.1 pad.1@3603.54,375.71 PP19.1 U1.J13 U1.J14 | length 16
  Bottom Layer w5: v1(4103.52,1361.97) C282.1@4103.52,1366.69
  Bottom Layer w8: C283.1@4127.06,1354.02 v1(4135.01,1361.97)
  other v1: 2265.75,277.87 2289.75,277.87 2265.75,300.87 2289.75,300.87
VDDIO: C59.3 C137.1 C138.1 C144.1 C147.1 C280.1 C281.1 pad.1@242.86,1686.82 pad.1@1936.7,144.81 PP17.1 R149.1 R151.1 SW3.3 U1.C9 U1.C10 U45.8 U46.14 U49.15 U50.5 U51.5 U53.15 | length 87.7
  Bottom Layer w8: v1(1227.12,1917.47) U53.15@1227.12,1926.14 ; R149.1@1529.29,2198.99 v1(1529.29,2207.66) ; U49.15@1603.83,1971.41 v1(1603.83,1976.41) ; v1(1932.53,1977.46) 1938.37,1983.3 1938.37,1988.8 1939.53,1989.95 U46.14@1939.53,2012.46 ; v1(2364.08,2271.38) R151.1@2369.08,2271.38 ; C280.1@4221.55,1165.04 v1(4229.5,1172.99) ; C281.1@4253.04,1165.04 v1(4261,1172.99)
  other v1: 2265.75,57.87 2289.75,57.87 2265.75,80.87 2289.75,80.87 1971.03,1802.71 1436.02,2176.95 1436.02,2256.95
VDDL: C83.1 C85.2 C86.2 C87.2 C88.2 C89.1 FB4.2 PP25.1 R67.1
VDDLA: C83.3 C276.1 C277.1 pad.1@2552.86,216.82 PP26.1 U1.F11 U1.H11 | length 9.4
  Bottom Layer w5: C277.1@4198,1258.04 C277.1@4198,1262.76 ; C276.1@4198,1325.75 v1(4198,1330.47)
  other v1: 2072.52,717.54 2072.52,742.54 4198,1267.48
VDDLB: C89.3 C278.1 C279.1 pad.1@1983.23,2478.31 PP27.1 U1.K11 U1.M11 | length 9.4
  Bottom Layer w5: v1(4198,1393.46) C279.1@4198,1398.19 ; v1(4198,1456.46) C278.1@4198,1461.18
  other v1: 2072.52,777.54 2072.52,802.54
VDDR18: C51.3 C284.1 pad.1@2415,1930 PP15.1 U1.N4 U1.P4 | length 11.2
  Bottom Layer w8: C284.1@4410.52,1495.91 v1(4418.48,1487.95)
  other v1: 2182.86,442.87 2206.86,442.87 2182.86,465.87 2206.86,465.87 4418.48,1519.45
VDDSP18: C60.3 C293.1 PP18.1 U1.J10
  other v1: 2182.86,222.87 2206.86,222.87 2182.86,245.87 2206.86,245.87 4229.5,1361.97
VDDSYS18: C57.3 C285.1 C286.1 pad.1@3551.34,382.78 PP16.1 U1.F14 U1.G14 | length 9.4
  Bottom Layer w5: C286.1@4098.79,1267.48 v1(4103.52,1267.48) ; C285.1@4098.79,1298.98 v1(4103.52,1298.98)
  other v1: 2182.86,112.87 2206.86,112.87 2182.86,135.87 2206.86,135.87
VEEAM18: C69.3 C300.1 C301.1 C302.1 C303.1 C304.1 C305.1 pad.1@2920.33,1074.9 U1.C12 U1.C13 U1.C14 U1.D12 U1.D13 U1.D14 | length 34.8
  Bottom Layer w5: C305.1@4098.79,1204.49 v1(4103.52,1204.49) ; C300.1@4103.52,1168.27 v1(4103.52,1172.99) ; C301.1@4135.01,1168.27 v1(4135.01,1172.99) ; C302.1@4166.51,1168.27 v1(4166.51,1172.99) ; v1(4166.51,1204.49) C303.1@4171.23,1204.49
  Bottom Layer w8: C304.1@4127.06,1212.44 v1(4135.01,1204.49)
  other v1: 1477.62,1157.22 1501.62,1157.22 1477.62,1180.22 1501.62,1180.22 1477.62,1203.22 1501.62,1203.22 1477.62,1226.22 1501.62,1226.22
VEEBM18: C77.3 C294.1 C295.1 C296.1 C297.1 C298.1 C299.1 pad.1@2627.86,2026.82 U1.P12 U1.P13 U1.P14 U1.R12 U1.R13 U1.R14 | length 41.4
  Bottom Layer w5: v1(4103.52,1550.94) C294.1@4103.52,1555.65 ; v1(4135.01,1550.94) C295.1@4135.01,1555.65 ; v1(4166.51,1519.45) C297.1@4171.21,1519.45 ; v1(4166.51,1550.94) C296.1@4166.51,1555.65
  Bottom Layer w8: C299.1@4095.56,1511.5 v1(4103.52,1519.45) ; C298.1@4127.06,1511.5 v1(4135.01,1519.45)
  other v1: 1632.44,1651.23 1656.44,1651.23 1632.43,1674.23 1656.43,1674.23 1632.44,1697.23 1656.44,1697.23 1632.43,1720.23 1656.43,1720.23
VSENSE-DVDD: R22.2 U6.7 | length 1674.9
  L10 SIG w5: v1(1131.81,1294.55) 1156.19,1270.17 1165.73,1270.17 1243.13,1192.77 1243.13,1090.76 1297.78,1036.11 1297.78,1034.81 1322.01,1010.58 1426.87,1010.58 1449.32,988.13 1471.29,988.13 1473.52,990.35 1488.11,990.35 1496.6,981.86 1496.6,961.08 1560.33,897.35 1835.29,897.35 1862.96,869.69 2187.1,869.69 2254.04,802.75 2462.28,802.75 v1(2483.78,824.25)
  Bottom Layer w5: U6.7@2478.78,799.25 2478.78,811.06 2481.3,813.57 2481.3,821.76 v1(2483.78,824.25)
  Bottom Layer w8: v1(1131.81,1294.55) R22.2@1131.81,1303.21
VSENSE-VDD18: R43.2 U6.5 | length 960
  L10 SIG w5: v1(1984.17,489.76) 2093.46,599.05 2239.03,599.05 2385.77,745.8 2427.47,745.8 2459.38,713.88 2528.41,713.88 2563.72,749.19 2563.72,815.59 2546.59,832.71 2522.01,832.71 2503.46,851.27 2474.3,851.27 v1(2442.29,819.25)
  Bottom Layer w5: R43.2@1984.17,481.1 v1(1984.17,489.76) ; v1(2442.29,819.25) 2442.29,816.06 2447.29,811.06 U6.5@2447.29,799.25
VSENSE-VDDCLK08: R78.2 U6.8 | length 389.7
  Top Layer w5: v1(2209.33,944.55) 2302.61,851.27 2413.36,851.27 2423.36,841.27 2495.57,841.27 2509.53,827.3 v1(2509.53,819.25)
  Bottom Layer w5: U6.8@2494.53,799.25 2494.53,807.12 2506.66,819.25 v1(2509.53,819.25)
  Bottom Layer w8: R78.2@2204.33,944.55 v1(2209.33,944.55)
VSENSE-VDDLx: R67.2 U6.9 | length 621.1
  L10 SIG w5: v1(1948.93,759.86) 2022.71,686.09 2307.34,686.09 2382.38,761.13 2405.42,761.13 2409.92,765.63 v1(2472.41,765.63)
  Bottom Layer w5: v1(2472.41,765.63) 2474.35,765.63 2481.83,773.12 2488.08,773.12 2490.59,775.63 U6.9@2502.41,775.63
VSENSE-VEEAM18: R58.2 U6.10 | length 1362.4
  L10 SIG w5: v1(1383.83,988.88) 1383.83,865.14 1443.17,805.8 1826.57,805.8 1853.49,832.71 2146.22,832.71 2187.55,791.38 2490.9,791.38 v1(2527.41,754.88)
  Bottom Layer w5: U6.10@2502.41,759.88 2514.22,759.88 2516.73,757.37 2524.92,757.37 v1(2527.41,754.88)
VSENSE-VEEBM18: R66.2 U6.3 | length 1280.1
  Top Layer w5: v1(1538.65,1482.89) 1603.74,1417.8 1603.74,1288.47 1632.43,1259.78 1741.53,1259.78 1775.09,1226.22 1817.61,1226.22 2102.75,941.07 2168.22,941.07 v1(2354.41,754.88)
  Bottom Layer w5: v1(2354.41,754.88) 2414.41,754.88 2416.9,757.37 2425.09,757.37 2427.6,759.88 U6.3@2439.41,759.88
VSENSE_CLOCKING: R89.2 U6.4 | length 1256.6
  Top Layer w5: v1(1948.93,1622.25) 1897.61,1570.92 1897.61,1438.57 1818.37,1359.34 1818.37,1243.78 2111.08,951.07 2172.36,951.07 2347.81,775.63 v1(2399.41,775.63)
  Bottom Layer w5: v1(2399.41,775.63) 2402.93,775.63 2407.93,780.63 2422.6,780.63 2427.6,775.63 U6.4@2439.41,775.63
  Bottom Layer w8: R89.2@1948.93,1617.25 v1(1948.93,1622.25)
pads on no net: FID1.1 FID2.1 FID3.1 H1. H3. H5.4 H6.4 J1. J1.A2 J1.A3 J1.A6 J1.A7 J1.A10 J1.A11 J1.A14 J1.A15 J1.A18 J1.A19 J1.B1 J1.B4 J1.B5 J1.B8 J1.B9 J1.B12 J1.B13 J1.B16 J1.B17 J1.C6 J1.C7 J1.C10 J1.C11 J1.C14 J1.C15 J1.C18 J1.C19 J1.D8 J1.D9 J1.D11 J1.D12 J1.D14 J1.D15 J1.D17 J1.D18 J1.D20 J1.D21 J1.D29 J1.D33 J1.D34 J1.E2 J1.E3 J1.E6 J1.E7 J1.E9 J1.E10 J1.E12 J1.E13 J1.E15 J1.E16 J1.E18 J1.E19 J1.E21 J1.E22 J1.E24 J1.E25 J1.E27 J1.E28 J1.E30 J1.E31 J1.E33 J1.E34 J1.E36 J1.E37 J1.F4 J1.F5 J1.F7 J1.F8 J1.F10 J1.F11 J1.F13 J1.F14 J1.F16 J1.F17 J1.F19 J1.F20 J1.F22 J1.F23 J1.F25 J1.F26 J1.F28 J1.F29 J1.F31 J1.F32 J1.F34 J1.F35 J1.F37 J1.F38 J1.G2 J1.G3 J1.G15 J1.G16 J1.G18 J1.G19 J1.G21 J1.G22 J1.G24 J1.G25 J1.H1 J1.H4 J1.H5 J1.H7 J1.H8 J1.H10 J1.H11 J1.H13 J1.H14 J1.H16 J1.H17 J1.H19 J1.H20 J1.H22 J1.H23 J1.H35 J1.H38 J1.J2 J1.J3 J1.J6 J1.J7 J1.J9 J1.J10 J1.J12 J1.J13 J1.J15 J1.J16 J1.J18 J1.J19 J1.J21 J1.J22 J1.J24 J1.J25 J1.J27 J1.J28 J1.J30 J1.J31 J1.J33 J1.J34 J1.J36 J1.J37 J1.J39 J1.K1 J1.K4 J1.K5 J1.K7 J1.K8 J1.K10 J1.K11 J1.K13 J1.K14 J1.K16 J1.K17 J1.K19 J1.K20 J1.K22 J1.K23 J1.K25 J1.K27 J1.K28 J1.K29 J1.K31 J1.K32 J1.K34 J1.K35 J1.K37 J1.K38 J1.K40 J1.L4 J1.L5 J1.L8 J1.L9 J1.L12 J1.L13 J1.L16 J1.L17 J1.L20 J1.L21 J1.L24 J1.L25 J1.L28 J1.L29 J1.M2 J1.M3 J1.M6 J1.M7 J1.M10 J1.M11 J1.M14 J1.M15 J1.M26 J1.M27 J1.M30 J1.M31 J1.M34 J1.M35 J1.M38 J1.M39 J1.Y2 J1.Y3 J1.Y10 J1.Y11 J1.Y14 J1.Y15 J1.Y18 J1.Y19 J1.Y22 J1.Y23 J1.Y34 J1.Y35 J1.Y38 J1.Y39 J1.Z4 J1.Z5 J1.Z12 J1.Z13 J1.Z16 J1.Z17 J1.Z20 J1.Z21 J1.Z32 J1.Z33 J1.Z36 J1.Z37 J3. J3.A5 J3.A8 J3.B5 J3.B8 Q1.0 Q2.1@1600.63,174.11 Q2.2@1584.88,174.11 Q3.1@1600.63,229.11 Q3.2@1584.88,229.11 T2.4 T4.4 T6.4 T8.4 U2.9 U3.0 U4.4 U5.2 U6.2 U7.8 U7.9 U8.5 U8.9 U8.10 U8.11 U10.2 U10.7 U10.8 U10.9 U10.30 U10.31 U10.32 U10.36 U10.45 U10.46 U11.6 U12.6 U13.4 U14.4 U17.1 U18.2 U18.11 U22.1 U23.2 U23.11 U28.6 U29.6 U31.6 U33.6 U37.21 U37.22 U37.23 U37.24 U37.29 U37.30 U37.32 U37.33 U37.36 U37.55 U37.57 U37.58 U37.59 U37.60 U40.6 U40.7 U41.4 U42.3 U42.6 U43.3@1156.57,2127.4 U43.8@1189.44,2127.4 U44.10 U44.11 U44.12 U44.13 U44.14 U44.15 U44.16 U44.17 U46.4 U46.6 U46.9 U47.6 U47.11 U54.1 U54.2 U54.3 U54.4 U54.7 U54.8 U54.9 U54.15 U54.16 U54.22 U54.23 U54.29 U54.30 U54.31 U54.32 U54.40 U54.41 U54.43 U54.44 U54.46 U54.48 U54.49 U54.50 U54.59 U54.60 U54.61 U54.62 U54.63 U60.3@5727.59,278.48 U60.8@5760.47,278.48

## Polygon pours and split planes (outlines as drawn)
GND on L14 PWR "NONET_L-01_P-001" (solid, remove dead copper, pour order 187): 52.59,3.8 cw(c52.59,53.8) 2.59,53.8 2.59,2670.34 cw(c52.59,2670.34) 52.59,2720.34 6152.59,2720.34 cw(c6152.59,2670.34) 6202.59,2670.34 6202.59,53.8 cw(c6152.59,53.8) 6152.59,3.8
VDDIO on L14 PWR "L14 PWR-VDDIO" (solid, remove dead copper, pour order 85): 1833.49,3.8 4447.61,3.8 4447.61,1208.8 4197.61,1208.8 4197.61,298.52 2672.32,298.52 2467.61,93.8 2042.61,93.8 2042.61,2093.8 2425.27,2093.8 2425.27,2289.12 2311.88,2289.12 2311.88,2193.8 1565.18,2193.8 1565.18,2277.62 1409.68,2277.62 1409.68,2193.8 1192.61,2193.8 1192.61,1833.8 2.61,1833.8 2.61,1628.8 1833.49,1628.8
EXTGND on L14 PWR "L14 PWR-EXTGND" (solid, remove dead copper, pour order 24): 690.91,3.8 690.91,482.76 545.74,482.76 545.74,770.14 2.59,770.14 2.59,53.8 ccw(c52.59,53.8) 52.59,3.8
VDDR18 on L14 PWR "NONET_L-01_P-001" (solid, remove dead copper, pour order 93): 2043.75,413.8 2043.75,2093.8 4452.61,2093.8 4452.61,1418.8 4302.61,1418.8 4302.61,1838.8 2262.61,1838.8 2262.61,413.8
3p3V_FTDI on L14 PWR "L14 PWR-3p3V_FTDI" (solid, remove dead copper, pour order 63): 182.61,1998.8 1037.61,1998.8 1037.61,2720.34 2.59,2720.34 2.59,2071.23 182.61,2071.23
VDDSYS18 on L14 PWR "L14 PWR-VDDSYS18" (solid, remove dead copper, pour order 122): 2042.61,93.8 2467.61,93.8 2672.32,298.52 4197.61,298.52 4197.61,1333.8 3972.61,1333.8 3972.61,1323.8 3089.35,440.55 2649.35,440.55 2397.61,188.8 2042.61,188.8
VDDSP18 on L14 PWR "NONET_L-01_P-001" (solid, remove dead copper, pour order 105): 2042.61,188.8 2042.61,298.8 2377.61,298.8 3487.61,1408.8 4287.61,1408.8 4287.61,1333.8 3977.61,1333.8 3084.35,440.55 2649.35,440.55 2397.61,188.8
VADJ on L14 PWR "L14 PWR-VADJ" (solid, remove dead copper, pour order 123): 2.59,1833.8 1192.61,1833.8 1192.61,2235.14 5487.61,2235.14 5487.61,363.8 5742.61,363.8 5742.61,2718.8 1192.61,2718.8 1192.61,2723.8 1037.61,2723.8 1037.61,1993.8 182.61,1993.8 182.61,2058.8 2.59,2058.8
3p3V_Utility on L14 PWR "NONET_L-01_P-001" (solid, remove dead copper, pour order 158): 1029.64,610.51 605.1,610.51 605.1,778.8 2.61,778.8 2.61,1602.9 1782.25,1602.9 1782.25,1002.63 860.91,1002.63 860.91,790.04 1029.64,790.04 1029.64,755.18
VDDCLK18 on L14 PWR "L14 PWR-VDDCLK18" (solid, remove dead copper, pour order 107): 2487.61,418.8 3477.61,1408.8 4302.61,1408.8 4302.61,1838.8 2372.61,1838.8 2372.61,1058.8 2297.61,1058.8 2297.61,413.8 2042.61,413.8 2042.61,298.8 2377.61,298.8 2487.61,408.8
2p3V on L14 PWR "L14 PWR-2p3V" (solid, remove dead copper, pour order 138): 860.91,790.04 1128.06,790.04 1128.06,298.8 1443.79,298.8 1443.79,298.48 1592.61,298.48 1592.61,1002.63 860.91,1002.63
3p3V_AUX on L14 PWR "gnd" (solid, remove dead copper, pour order 89): 6102.59,146.73 5893.77,146.73 5893.77,663.8 5737.59,663.8 5737.59,842.53 6102.59,842.53
VCORE on L14 PWR "L10 PWR-VCORE" (solid, remove dead copper, pour order 58): 1026.57,2176.31 1026.57,2521 715.52,2521 715.52,2543 547.59,2543 547.59,2183.34 715.52,2183.34 715.52,2464.65 954.1,2464.65 954.1,2255.86 922.59,2255.86 922.59,2176.31
GND on L12 PWR "NONET_L-01_P-001" (solid, remove dead copper, pour order 186): 52.59,3.8 cw(c52.59,53.8) 2.59,53.8 2.59,2670.34 cw(c52.59,2670.34) 52.59,2720.34 6152.59,2720.34 cw(c6152.59,2670.34) 6202.59,2670.34 6202.59,53.8 cw(c6152.59,53.8) 6152.59,3.8
VDD_FPGA on L12 PWR "NONET_L-01_P-001" (solid, remove dead copper, pour order 16): 2122.61,1775.25 2122.61,2295.07 2.61,2295.07 2.61,1775.25
VDDA18A on L12 PWR "L12 PWR-VDDA18A" (solid, remove dead copper, pour order 13): 2047.61,348.8 2309.21,348.8 2309.21,481.06 4449.97,481.06 4449.97,1330.47 3963.46,1330.47 3963.46,1248.8 4254.03,1248.8 4254.03,805.7 2047.61,805.7 2047.61,481.06
EXTGND on L12 PWR "NONET_L-01_P-001" (solid, remove dead copper, pour order 75): 690.91,770.14 2.59,770.14 2.59,53.8 ccw(c52.59,53.8) 52.59,3.8 690.91,3.8
VEEBM18 on L12 PWR "L12 PWR-VEEBM18" (solid, remove dead copper, pour order 127): 1580.36,1618.8 2332.61,1618.8 2332.61,1838.8 3072.61,1838.8 3072.61,1488.8 4212.61,1488.8 4212.61,1858.8 3737.61,1858.8 3737.61,2300.42 2060.72,2300.42 2060.72,1775.25 1580.36,1775.25
VEEAM18 on L12 PWR "L12 PWR-VEEAM18" (solid, remove dead copper, pour order 170): 1407.61,837.68 4213.19,837.68 4213.19,1215.18 1588.7,1215.18 1588.7,1306.87 1407.61,1306.87 1407.61,1215.18 1407.24,1112.82 1407.61,1112.82
3p3V_Utility on L12 PWR "NONET_L-01_P-001" (solid, remove dead copper, pour order 137): 628.96,2718.8 628.96,2406.77 4742.61,2406.77 4742.61,2250.21 6202.59,2250.21 6202.59,2724.96
VDDA18B on L12 PWR "L12 PWR-VDDA18B" (solid, remove dead copper, pour order 169): 2047.61,3.8 5147.61,3.8 5147.61,2078.73 3927.61,2078.73 3927.61,1873.8 4227.61,1873.8 4227.61,1488.8 3962.61,1488.8 3962.61,1393.8 4817.61,1393.8 4817.61,309.82 2517.98,309.82 2517.98,208.8 2047.61,208.8
VDDCP18 on L12 PWR "L12 PWR-VDDCP18" (solid, remove dead copper, pour order 167): 2047.61,221.04 2517.98,221.04 2517.98,309.82 4817.61,309.82 4817.61,1393.8 3962.61,1393.8 3962.61,1328.8 4452.61,1328.8 4452.61,481.06 2309.55,481.06 2309.55,348.8 2047.61,348.8
3p3V_Clock on L12 PWR "NONET_L-01_P-001" (solid, remove dead copper, pour order 111): 1837.61,1233.8 1837.61,1528.8 2332.61,1528.8 2332.61,1793.8 2992.61,1793.8 2992.61,1233.8 2047.61,1233.8
3p3V_FMC on L12 PWR "L8 SIG-3p3V_FMC" (solid, remove dead copper, pour order 70): 5664.01,3.8 6102.59,3.8 6102.59,598.8 5727.59,598.8 5727.59,353.8 5664.01,353.8
3p3V_EEPROM on L12 PWR "gnd" (solid, remove dead copper, pour order 46): 5747.61,294.09 5747.61,103.8 5897.59,103.8 5897.59,294.09
GND on L2 GND "NONET_L-01_P-001" (solid, remove dead copper, pour order 174): 52.59,3.8 cw(c52.59,53.8) 2.59,53.8 2.59,2670.34 cw(c52.59,2670.34) 52.59,2720.34 6152.59,2720.34 cw(c6152.59,2670.34) 6202.59,2670.34 6202.59,53.8 cw(c6152.59,53.8) 6152.59,3.8
EXTGND on L2 GND "NONET_L-01_P-001" (solid, remove dead copper, pour order 67): 690.91,770.14 2.59,770.14 2.59,53.8 ccw(c52.59,53.8) 52.59,3.8 690.91,3.8
GND on L6 GND "L6 GND-GND" (solid, remove dead copper, pour order 43): 4471.26,3.8 6202.59,3.8 6202.59,2720.34 559.13,2720.34 ccw(c559.12,2663.84) 539.24,2716.72 59.13,2716.72 ccw(c59.13,2660.19) 2.59,2660.19 2.59,50.19 ccw(c52.59,50.19) 52.59,0.19 4452.59,0.19 ccw(c4452.59,50.18)
EXTGND on L6 GND "NONET_L-01_P-001" (solid, remove dead copper, pour order 9): 690.91,770.14 2.59,770.14 2.59,53.8 ccw(c52.59,53.8) 52.59,3.8 690.91,3.8
GND on L4 GND "NONET_L-01_P-001" (solid, remove dead copper, pour order 141): 52.59,3.8 cw(c52.59,53.8) 2.59,53.8 2.59,2670.34 cw(c52.59,2670.34) 52.59,2720.34 6152.59,2720.34 cw(c6152.59,2670.34) 6202.59,2670.34 6202.59,53.8 cw(c6152.59,53.8) 6152.59,3.8
EXTGND on L4 GND "NONET_L-01_P-001" (solid, remove dead copper, pour order 8): 690.91,770.14 2.59,770.14 2.59,53.8 ccw(c52.59,53.8) 52.59,3.8 690.91,3.8
GND on L11 GND "NONET_L-01_P-001" (solid, remove dead copper, pour order 146): 52.59,3.8 cw(c52.59,53.8) 2.59,53.8 2.59,2670.34 cw(c52.59,2670.34) 52.59,2720.34 6152.59,2720.34 cw(c6152.59,2670.34) 6202.59,2670.34 6202.59,53.8 cw(c6152.59,53.8) 6152.59,3.8
EXTGND on L11 GND "NONET_L-01_P-001" (solid, remove dead copper, pour order 10): 690.91,770.14 2.59,770.14 2.59,53.8 ccw(c52.59,53.8) 52.59,3.8 690.91,3.8
GND on L3 PWR "NONET_L-01_P-001" (solid, remove dead copper, pour order 184): 52.59,3.8 cw(c52.59,53.8) 2.59,53.8 2.59,2670.34 cw(c52.59,2670.34) 52.59,2720.34 6152.59,2720.34 cw(c6152.59,2670.34) 6202.59,2670.34 6202.59,53.8 cw(c6152.59,53.8) 6152.59,3.8
DVDD on L3 PWR "NONET_L-01_P-001" (solid, remove dead copper, pour order 68): 932.61,1908.8 932.61,777.54 5327.61,777.54 5327.61,2720.34 932.61,2720.34
12V_FMC on L3 PWR "L3 PWR-12V_FMC" (solid, remove dead copper, pour order 27): 5892.6,1.29 5892.6,693.86 5361.36,693.86 5361.36,378.8 999.9,378.8 999.9,1.29
12V on L3 PWR "L3 PWR-12V" (solid, remove dead copper, pour order 101): 7.59,-1.2 999.9,-1.2 999.9,378.8 5242.61,378.8 5242.61,593.8 860.91,593.8 860.91,1918.8 2.59,1918.8 2.59,53.81 ccw(c52.6,53.81) 7.59,32.01
EXTGND on L3 PWR "NONET_L-01_P-001" (solid, remove dead copper, pour order 61): 675.69,770.14 2.59,770.14 2.59,185.83 675.69,185.83
GND on L13 GND "NONET_L-01_P-001" (solid, remove dead copper, pour order 145): 52.59,3.8 cw(c52.59,53.8) 2.59,53.8 2.59,2670.34 cw(c52.59,2670.34) 52.59,2720.34 6152.59,2720.34 cw(c6152.59,2670.34) 6202.59,2670.34 6202.59,53.8 cw(c6152.59,53.8) 6152.59,3.8
EXTGND on L13 GND "NONET_L-01_P-001" (solid, remove dead copper, pour order 11): 690.91,770.14 2.59,770.14 2.59,53.8 ccw(c52.59,53.8) 52.59,3.8 690.91,3.8
GND on L15 GND "NONET_L-01_P-001" (solid, remove dead copper, pour order 144): 52.59,3.8 cw(c52.59,53.8) 2.59,53.8 2.59,2670.34 cw(c52.59,2670.34) 52.59,2720.34 6152.59,2720.34 cw(c6152.59,2670.34) 6202.59,2670.34 6202.59,53.8 cw(c6152.59,53.8) 6152.59,3.8
EXTGND on L15 GND "NONET_L-01_P-001" (solid, remove dead copper, pour order 12): 690.91,770.14 2.59,770.14 2.59,53.8 ccw(c52.59,53.8) 52.59,3.8 690.91,3.8
GND on L5 PWR "NONET_L-01_P-001" (solid, remove dead copper, pour order 185): 52.59,3.8 cw(c52.59,53.8) 2.59,53.8 2.59,2670.34 cw(c52.59,2670.34) 52.59,2720.34 6152.59,2720.34 cw(c6152.59,2670.34) 6202.59,2670.34 6202.59,53.8 cw(c6152.59,53.8) 6152.59,3.8
VDDLB on L5 PWR "NONET_L-01_P-001" (solid, remove dead copper, pour order 65): 2177.61,763.8 2177.61,868.8 1857.61,868.8 1857.61,2163.8 4182.61,2163.8 4182.61,1378.8 5582.61,1378.8 5582.61,2718.8 1167.61,2718.8 1167.61,763.8
VDDLA on L5 PWR "NONET_L-01_P-001" (solid, remove dead copper, pour order 69): 1782.61,758.8 1782.61,3.8 5582.61,3.8 5582.61,1348.8 4177.61,1348.8 4177.61,758.8
EXTGND on L5 PWR "NONET_L-01_P-001" (solid, remove dead copper, pour order 64): 690.91,770.14 2.59,770.14 2.59,53.8 ccw(c52.59,53.8) 52.59,3.8 690.91,3.8
VDDCLK08 on L5 PWR "L5 PWR-VDDCLK08" (solid, remove dead copper, pour order 42): 4184.84,1348.8 4214.42,1348.8 4214.42,1373.8 4186.17,1373.8 4177.61,1382.37 4177.61,1492.59 3658.15,2012.05 2125.31,2012.05 2125.31,928.8 3859.32,928.8 4177.61,1247.08 4177.61,1341.57
GND on L9 GND "NONET_L-01_P-001" (solid, remove dead copper, pour order 147): 52.59,3.8 cw(c52.59,53.8) 2.59,53.8 2.59,2670.34 cw(c52.59,2670.34) 52.59,2720.34 6152.59,2720.34 cw(c6152.59,2670.34) 6202.59,2670.34 6202.59,53.8 cw(c6152.59,53.8) 6152.59,3.8
EXTGND on L9 GND "NONET_L-01_P-001" (solid, remove dead copper, pour order 52): 690.91,770.14 2.59,770.14 2.59,53.8 ccw(c52.59,53.8) 52.59,3.8 690.91,3.8
GND on L8 GND "NONET_L-01_P-001" (solid, remove dead copper, pour order 148): 52.59,3.8 cw(c52.59,53.8) 2.59,53.8 2.59,2670.34 cw(c52.59,2670.34) 52.59,2720.34 6152.59,2720.34 cw(c6152.59,2670.34) 6202.59,2670.34 6202.59,53.8 cw(c6152.59,53.8) 6152.59,3.8
EXTGND on L8 GND "NONET_L-01_P-001" (solid, remove dead copper, pour order 53): 690.91,770.14 2.59,770.14 2.59,53.8 ccw(c52.59,53.8) 52.59,3.8 690.91,3.8
GND on L7 SIG "NONET_L-01_P-001" (solid, remove dead copper, pour order 188): 52.59,3.8 cw(c52.59,53.8) 2.59,53.8 2.59,2670.34 cw(c52.59,2670.34) 52.59,2720.34 6152.59,2720.34 cw(c6152.59,2670.34) 6202.59,2670.34 6202.59,53.8 cw(c6152.59,53.8) 6152.59,3.8
3p3V_Utility on L7 SIG "L7 SIG-3p3V_Utility" (solid, remove dead copper, pour order 132): -2.39,768.8 701.64,768.8 701.64,3.8 6107.61,3.8 6107.61,128.8 4707.61,128.8 4229.85,606.55 2873.3,606.55 2873.3,1158.8 862.61,1158.8 862.61,1843.8 1087.61,1843.8 1087.61,1710.64 1880.15,1710.64 1931.66,1762.15 1931.66,2375.69 1877.36,2429.99 1621.61,2429.99 1480.99,2289.38 1480.99,2045.73 1421.52,1986.26 1421.52,1960.26 1505.21,1876.57 1505.21,1851.87 1212.61,1851.87 1212.61,2125.12 1172.61,2165.12 1172.61,2203.8 1227.61,2258.8 1227.61,2628.8 1282.61,2683.8 1282.61,2718.8 -2.39,2718.8
3p8V on L7 SIG "L7 SIG-3p8V" (solid, remove dead copper, pour order 154): 865.71,1157.22 1745.94,1157.22 1745.94,1376.59 1479.59,1376.59 1479.59,1711.58 1098.37,1711.58 1098.37,1842.24 865.71,1842.24
EXTGND on L7 SIG "NONET_L-01_P-001" (solid, remove dead copper, pour order 54): 690.91,770.14 2.59,770.14 2.59,53.8 ccw(c52.59,53.8) 52.59,3.8 690.91,3.8
GND on L10 SIG "NONET_L-01_P-001" (solid, remove dead copper, pour order 190): 52.59,3.8 cw(c52.59,53.8) 2.59,53.8 2.59,2670.34 cw(c52.59,2670.34) 52.59,2720.34 6152.59,2720.34 cw(c6152.59,2670.34) 6202.59,2670.34 6202.59,53.8 cw(c6152.59,53.8) 6152.59,3.8
3p3V_Utility on L10 SIG "NONET_L-01_P-001" (solid, remove dead copper, pour order 126): 1247.39,1460.84 1297.12,1460.84 1342.87,1506.59 1342.87,1803.66 1309.32,1837.21 1178.02,1837.21 1156.19,1815.38 1156.19,1552.05
EXTGND on L10 SIG "NONET_L-01_P-001" (solid, remove dead copper, pour order 57): 690.91,770.14 2.59,770.14 2.59,53.8 ccw(c52.59,53.8) 52.59,3.8 690.91,3.8
GND on Top Layer "NONET_L-01_P-001" (solid, remove dead copper, pour order 152): 52.59,3.8 cw(c52.59,53.8) 2.59,53.8 2.59,2670.34 cw(c52.59,2670.34) 52.59,2720.34 6152.59,2720.34 cw(c6152.59,2670.34) 6202.59,2670.34 6202.59,53.8 cw(c6152.59,53.8) 6152.59,3.8
EXTGND on Top Layer "NONET_L-01_P-001" (solid, remove dead copper, pour order 140): 690.91,770.14 2.59,770.14 2.59,53.8 ccw(c52.59,53.8) 52.59,3.8 690.91,3.8
GND on Bottom Layer "NONET_L-01_P-001" (solid, remove dead copper, pour order 179): 52.59,3.8 cw(c52.59,53.8) 2.59,53.8 2.59,2670.34 cw(c52.59,2670.34) 52.59,2720.34 6152.59,2720.34 cw(c6152.59,2670.34) 6202.59,2670.34 6202.59,53.8 cw(c6152.59,53.8) 6152.59,3.8

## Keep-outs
Keep-Out Layer:
  text ".Layer_Name" at 579.59,-854.69 h60

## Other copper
Top Layer:
  drawing of 123 lines, arcs and shapes, not listed
  text ".Layer_Name" at 579.59,-854.69 h60
L2 GND:
  pour cut-out: 4198,1117 ccw(c4198,1110) 4205,1110 ccw(c4198,1110)
  pour cut-out: 4135.01,1117 ccw(c4135.01,1110) 4142.01,1110 ccw(c4135.01,1110)
  pour cut-out: 4072.02,1117 ccw(c4072.02,1110) 4079.02,1110 ccw(c4072.02,1110)
  pour cut-out: 4040.52,1117 ccw(c4040.52,1110) 4047.52,1110 ccw(c4040.52,1110)
  pour cut-out: 4009.03,1211.49 ccw(c4009.03,1204.49) 4016.03,1204.49 ccw(c4009.03,1204.49)
  pour cut-out: 4009.03,1242.98 ccw(c4009.03,1235.98) 4016.03,1235.98 ccw(c4009.03,1235.98)
  pour cut-out: 4009.03,1494.95 ccw(c4009.03,1487.95) 4016.03,1487.95 ccw(c4009.03,1487.95)
  pour cut-out: 4009.03,1526.45 ccw(c4009.03,1519.45) 4016.03,1519.45 ccw(c4009.03,1519.45)
  pour cut-out: 4040.52,1620.94 ccw(c4040.52,1613.94) 4047.52,1613.94 ccw(c4040.52,1613.94)
  pour cut-out: 4072.02,1620.94 ccw(c4072.02,1613.94) 4079.02,1613.94 ccw(c4072.02,1613.94)
  pour cut-out: 4198,1620.94 ccw(c4198,1613.94) 4205,1613.94 ccw(c4198,1613.94)
  pour cut-out: 4135.01,1620.94 ccw(c4135.01,1613.94) 4142.01,1613.94 ccw(c4135.01,1613.94)
  pour cut-out: 4090,1974.84 4130,1974.84 4130,2004.84 4090,2004.84
  pour cut-out: 4303.02,1974.84 4343.02,1974.84 4343.02,2004.84 4303.02,2004.84
  pour cut-out: 4303.02,1868.94 4343.02,1868.94 4343.02,1898.94 4303.02,1898.94
  pour cut-out: 4090,1868.94 4130,1868.94 4130,1898.94 4090,1898.94
  pour cut-out: 3990,719.09 4030,719.09 4030,749.09 3990,749.09
  pour cut-out: 4203.02,719.09 4243.02,719.09 4243.02,749.09 4203.02,749.09
  pour cut-out: 4203.02,825 4243.02,825 4243.02,855 4203.02,855
  pour cut-out: 3990,825 4030,825 4030,855 3990,855
  pour cut-out: 3402.48,1536.7 3402.48,1560.7 3430.48,1560.7 3437.48,1553.7 3437.48,1543.7 3430.48,1536.7
  pour cut-out: 3776.48,1470.7 3776.48,1446.7 3748.48,1446.7 3741.48,1453.7 3741.48,1463.7 3748.48,1470.7
  pour cut-out: 3776.48,1560.7 3776.48,1536.7 3748.48,1536.7 3741.48,1543.7 3741.48,1553.7 3748.48,1560.7
  text ".Layer_Name" at 577.59,-856.2 h60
